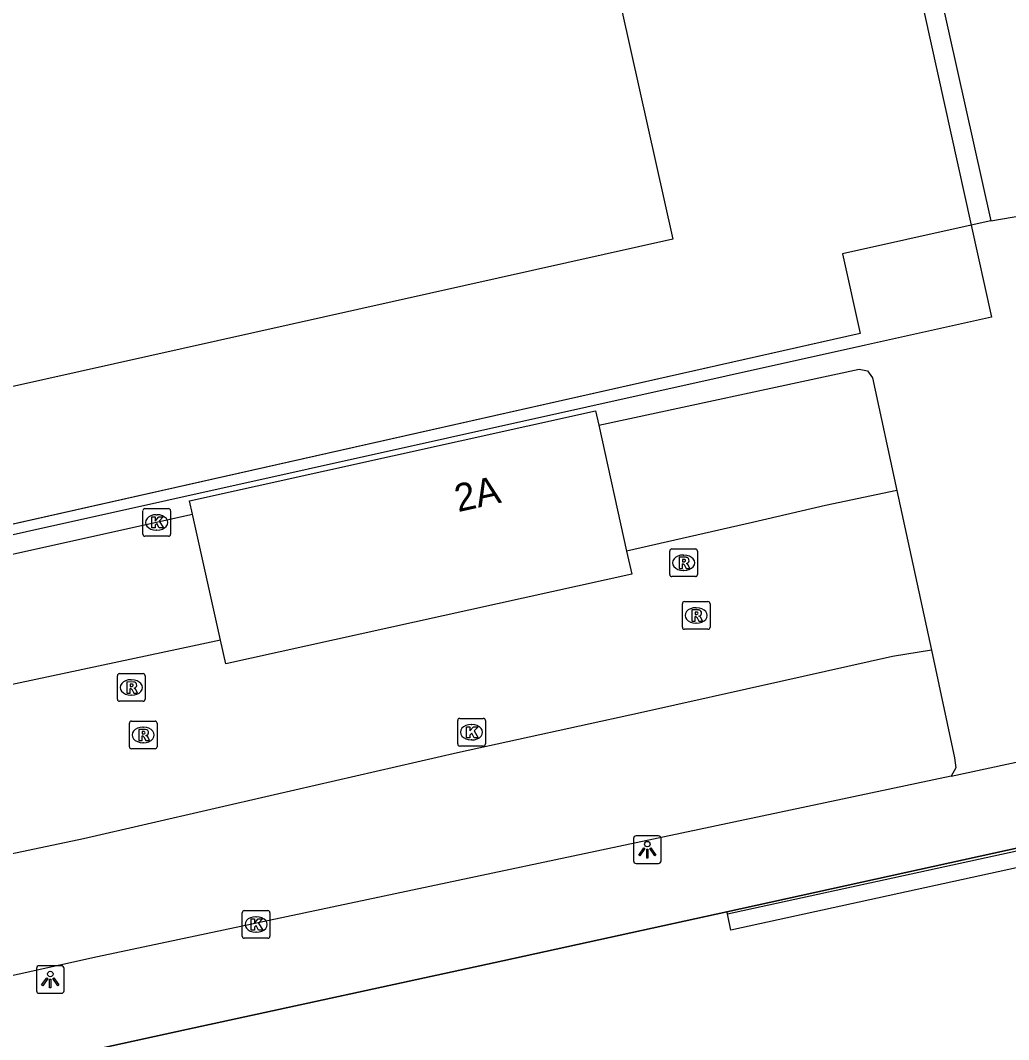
# Model space of a CAD drawing. Extents: x 160806 to 161707, y 383697 to 384148.
# Drawn here: x 161645.05 to 161680.77, y 383862.05 to 383898.89 of the extents above; entities that cross this region are included whole.
import ezdxf

# ---------------------------------------------------------------- set-up
doc = ezdxf.new("R2010")
doc.units = 0
for name, color, linetype in [('IMGEO_Grasland_overig', 7, 'Continuous'), ('IMGEO_Groenvoorziening', 7, 'Continuous'), ('IMGEO_Hek', 7, 'Continuous'), ('IMGEO_Kolk', 7, 'Continuous'), ('IMGEO_Lichtpunt', 7, 'Continuous'), ('IMGEO_Pand', 7, 'Continuous'), ('IMGEO_Pand_nummerreeks', 7, 'Continuous'), ('IMGEO_Parkeervlak_open', 7, 'Continuous'), ('IMGEO_Rijbaan_lokaal_open', 7, 'Continuous'), ('IMGEO_Rioolput', 7, 'Continuous'), ('IMGEO_Spoorbaan_halfverhard', 7, 'Continuous'), ('IMGEO_Terreindeel_gesloten', 7, 'Continuous')]:
    doc.layers.add(name, color=color, linetype=linetype)

msp = doc.modelspace()

# ---------------------------------------------------------------- linework, layer by layer
at = {"layer": 'IMGEO_Grasland_overig'}
msp.add_lwpolyline([(161679.423, 383891.492), (161680.158, 383888.167), (161675.596, 383887.152), (161635.195, 383878.161), (161630.532, 383877.228), (161606.363, 383871.769)], dxfattribs=at)
at = {"layer": 'IMGEO_Groenvoorziening'}
for points in [[(161661.841, 383973.012), (161664.529, 383961.571), (161680.134, 383891.651)], [(161680.134, 383891.651), (161686.383, 383892.722)], [(161680.134, 383891.651), (161679.423, 383891.492)], [(161678.693, 383871.571), (161692.17, 383874.476), (161696.167, 383872.737)], [(161692.46, 383871.911), (161687.731, 383870.454), (161682.93, 383869.376), (161670.593, 383866.669)]]:
    msp.add_lwpolyline(points, dxfattribs=at)
at = {"layer": 'IMGEO_Hek'}
for points in [[(161679.423, 383891.492), (161674.766, 383890.452), (161675.408, 383887.573), (161592.484, 383868.91)], [(161468.352, 383821.972), (161470.021, 383822.345), (161472.634, 383822.879), (161475.023, 383823.371), (161479.934, 383824.467), (161509.272, 383830.942), (161514.217, 383832.035), (161521.635, 383833.723), (161580.201, 383846.689), (161582.51, 383847.687), (161585.012, 383847.75), (161614.342, 383854.325), (161641.301, 383860.274), (161651.06, 383862.411), (161662.497, 383864.892), (161670.593, 383866.669), (161682.93, 383869.376), (161687.731, 383870.454), (161692.46, 383871.911), (161696.167, 383872.737)]]:
    msp.add_lwpolyline(points, dxfattribs=at)
at = {"layer": 'IMGEO_Kolk'}
for p, q in [((161649.479, 383880.317), (161649.479, 383881.169)), ((161649.554, 383881.243), (161650.406, 383881.243)), ((161650.48, 383881.169), (161650.48, 383880.317)), ((161649.967, 383881.023), (161649.992, 383881.023)), ((161649.99, 383880.463), (161649.965, 383880.463)), ((161650.406, 383880.243), (161649.554, 383880.243)), ((161660.935, 383873.66), (161661.787, 383873.66)), ((161660.86, 383872.734), (161660.86, 383873.586)), ((161661.348, 383873.44), (161661.373, 383873.44)), ((161661.861, 383873.586), (161661.861, 383872.734)), ((161661.787, 383872.66), (161660.935, 383872.66)), ((161661.371, 383872.88), (161661.346, 383872.88)), ((161653.148, 383866.709), (161654, 383866.709)), ((161653.073, 383865.783), (161653.073, 383866.635)), ((161653.561, 383866.489), (161653.586, 383866.489)), ((161654.074, 383866.635), (161654.074, 383865.783)), ((161653.584, 383865.929), (161653.559, 383865.929)), ((161654, 383865.709), (161653.148, 383865.709))]:
    msp.add_line(p, q, dxfattribs=at)
for points in [[(161649.479, 383880.317), (161649.479, 383881.169)], [(161649.554, 383881.243), (161650.406, 383881.243)], [(161650.48, 383881.169), (161650.48, 383880.317)], [(161649.8, 383880.943), (161649.923, 383880.943), (161649.923, 383880.792), (161650.053, 383880.943), (161650.217, 383880.943), (161650.071, 383880.792), (161650.224, 383880.543), (161650.072, 383880.543), (161649.987, 383880.707), (161649.923, 383880.64), (161649.923, 383880.543), (161649.8, 383880.543), (161649.8, 383880.943)], [(161650.406, 383880.243), (161649.554, 383880.243)], [(161660.935, 383873.66), (161661.787, 383873.66)], [(161660.86, 383872.734), (161660.86, 383873.586)], [(161661.181, 383873.36), (161661.304, 383873.36), (161661.304, 383873.209), (161661.434, 383873.36), (161661.598, 383873.36), (161661.452, 383873.209), (161661.605, 383872.96), (161661.453, 383872.96), (161661.368, 383873.124), (161661.304, 383873.057), (161661.304, 383872.96), (161661.181, 383872.96), (161661.181, 383873.36)], [(161661.861, 383873.586), (161661.861, 383872.734)], [(161661.787, 383872.66), (161660.935, 383872.66)], [(161653.148, 383866.709), (161654, 383866.709)], [(161653.073, 383865.783), (161653.073, 383866.635)], [(161653.394, 383866.409), (161653.517, 383866.409), (161653.517, 383866.258), (161653.647, 383866.409), (161653.811, 383866.409), (161653.665, 383866.258), (161653.818, 383866.009), (161653.666, 383866.009), (161653.581, 383866.173), (161653.517, 383866.106), (161653.517, 383866.009), (161653.394, 383866.009), (161653.394, 383866.409)], [(161654.074, 383866.635), (161654.074, 383865.783)], [(161654, 383865.709), (161653.148, 383865.709)]]:
    msp.add_lwpolyline(points, dxfattribs=at)
for centre, start, end in [((161649.556, 383881.167), 91.552, 178.448), ((161649.556, 383881.167), 91.552, 178.448), ((161650.404, 383881.167), 1.552, 88.448), ((161650.404, 383881.167), 1.552, 88.448), ((161649.556, 383880.319), 181.552, 268.448), ((161649.556, 383880.319), 181.552, 268.448), ((161650.404, 383880.319), 271.552, 358.448), ((161650.404, 383880.319), 271.552, 358.448), ((161660.937, 383873.584), 91.552, 178.448), ((161660.937, 383873.584), 91.552, 178.448), ((161661.785, 383873.584), 1.552, 88.448), ((161661.785, 383873.584), 1.552, 88.448), ((161660.937, 383872.736), 181.552, 268.448), ((161660.937, 383872.736), 181.552, 268.448), ((161661.785, 383872.736), 271.552, 358.448), ((161661.785, 383872.736), 271.552, 358.448), ((161653.15, 383866.633), 91.552, 178.448), ((161653.15, 383866.633), 91.552, 178.448), ((161653.998, 383866.633), 1.552, 88.448), ((161653.998, 383866.633), 1.552, 88.448), ((161653.15, 383865.785), 181.552, 268.448), ((161653.15, 383865.785), 181.552, 268.448), ((161653.998, 383865.785), 271.552, 358.448), ((161653.998, 383865.785), 271.552, 358.448)]:
    msp.add_arc(centre, 0.0765, start, end, dxfattribs=at)
for centre, major_axis, ratio, start_param, end_param in [((161649.966, 383880.743), (-0.387, 0.002), 0.722429, 4.712389, 7.853982), ((161649.991, 383880.743), (-0.39, 0.002), 0.717154, 1.570796, 4.712389), ((161661.347, 383873.16), (-0.387, 0.002), 0.722429, 4.712389, 7.853982), ((161661.372, 383873.16), (-0.39, 0.002), 0.717154, 1.570796, 4.712389), ((161653.56, 383866.209), (-0.387, 0.002), 0.722429, 4.712389, 7.853982), ((161653.585, 383866.209), (-0.39, 0.002), 0.717154, 1.570796, 4.712389)]:
    msp.add_ellipse(centre, major_axis=major_axis, ratio=ratio, start_param=start_param, end_param=end_param, dxfattribs=at)
at = {"layer": 'IMGEO_Lichtpunt'}
for p, q in [((161667.216, 383869.317), (161667.216, 383868.51)), ((161667.216, 383869.317), (161667.216, 383868.51)), ((161668.118, 383869.412), (161667.31, 383869.412)), ((161668.118, 383869.412), (161667.31, 383869.412)), ((161668.212, 383868.51), (161668.212, 383869.317)), ((161668.212, 383868.51), (161668.212, 383869.317)), ((161667.31, 383868.416), (161668.118, 383868.416)), ((161667.31, 383868.416), (161668.118, 383868.416)), ((161645.636, 383864.622), (161645.636, 383863.815)), ((161645.636, 383864.622), (161645.636, 383863.815)), ((161646.538, 383864.717), (161645.73, 383864.717)), ((161646.538, 383864.717), (161645.73, 383864.717)), ((161646.632, 383863.815), (161646.632, 383864.622)), ((161646.632, 383863.815), (161646.632, 383864.622)), ((161645.73, 383863.721), (161646.538, 383863.721)), ((161645.73, 383863.721), (161646.538, 383863.721))]:
    msp.add_line(p, q, dxfattribs=at)
for points in [[(161667.59, 383868.981), (161667.629, 383868.953), (161667.441, 383868.691), (161667.403, 383868.718), (161667.59, 383868.981)], [(161667.692, 383868.933), (161667.739, 383868.933), (161667.739, 383868.611), (161667.692, 383868.611), (161667.692, 383868.933)], [(161667.802, 383868.953), (161667.84, 383868.98), (161668.027, 383868.718), (161667.988, 383868.69), (161667.802, 383868.953)], [(161646.01, 383864.286), (161646.049, 383864.258), (161645.861, 383863.996), (161645.823, 383864.023), (161646.01, 383864.286)], [(161646.112, 383864.238), (161646.159, 383864.238), (161646.159, 383863.916), (161646.112, 383863.916), (161646.112, 383864.238)], [(161646.222, 383864.258), (161646.26, 383864.285), (161646.447, 383864.023), (161646.408, 383863.995), (161646.222, 383864.258)]]:
    msp.add_lwpolyline(points, dxfattribs=at)
for centre in [(161667.715, 383869.115), (161646.135, 383864.42)]:
    msp.add_circle(centre, 0.0994, dxfattribs=at)
for centre, start, end in [((161667.31, 383869.317), 90, 180), ((161667.31, 383869.317), 90, 180), ((161668.118, 383869.317), 0, 90), ((161668.118, 383869.317), 0, 90), ((161667.31, 383868.51), 180, 270), ((161667.31, 383868.51), 180, 270), ((161668.118, 383868.51), 270, 0), ((161668.118, 383868.51), 270, 360), ((161645.73, 383864.622), 90, 180), ((161645.73, 383864.622), 90, 180), ((161646.538, 383864.622), 0, 90), ((161646.538, 383864.622), 0, 90), ((161645.73, 383863.815), 180, 270), ((161645.73, 383863.815), 180, 270), ((161646.538, 383863.815), 270, 0), ((161646.538, 383863.815), 270, 360)]:
    msp.add_arc(centre, 0.0946, start, end, dxfattribs=at)
at = {"layer": 'IMGEO_Pand'}
for points in [[(161636.5, 383961.134), (161636.09, 383962.971), (161636.41, 383963.042), (161651.22, 383966.246), (161651.275, 383966.421), (161651.781, 383966.534), (161668.642, 383890.98), (161623.195, 383880.838), (161623.29, 383880.412), (161614.09, 383878.359)], [(161651.274, 383881.048), (161651.168, 383881.526), (161665.845, 383884.775), (161665.96, 383884.257)], [(161665.96, 383884.257), (161666.967, 383879.708)], [(161652.29, 383876.485), (161651.274, 383881.048)], [(161666.967, 383879.708), (161667.151, 383878.878), (161652.481, 383875.629), (161652.29, 383876.485)]]:
    msp.add_lwpolyline(points, dxfattribs=at)
at = {"layer": 'IMGEO_Parkeervlak_open'}
for points in [[(161665.96, 383884.257), (161675.376, 383886.281), (161675.673, 383886.219), (161675.855, 383885.976), (161676.735, 383881.898)], [(161606.519, 383871.073), (161626.185, 383875.445), (161628.76, 383876.043), (161651.274, 383881.048)], [(161677.981, 383876.124), (161678.822, 383872.229), (161678.868, 383871.878), (161678.693, 383871.571)], [(161678.693, 383871.571), (161647.839, 383865.039), (161626.972, 383860.422), (161609.694, 383856.527), (161595.494, 383853.326)]]:
    msp.add_lwpolyline(points, dxfattribs=at)
at = {"layer": 'IMGEO_Rijbaan_lokaal_open'}
for points in [[(161655.739, 383972.541), (161658.016, 383963.339), (161663.04, 383964.457), (161672.626, 383922.253), (161679.423, 383891.492)], [(161679.423, 383891.492), (161674.766, 383890.452), (161675.408, 383887.573), (161606.306, 383872.021)], [(161676.735, 383881.898), (161674.153, 383881.35), (161671.512, 383880.738), (161666.967, 383879.708)], [(161676.735, 383881.898), (161677.981, 383876.124)], [(161652.29, 383876.485), (161651.442, 383876.303), (161629.63, 383871.673), (161606.594, 383866.552), (161606.493, 383866.529), (161603.52, 383865.895), (161591.531, 383863.209)], [(161677.981, 383876.124), (161676.579, 383875.892), (161672.537, 383874.994), (161667.473, 383873.86), (161660.853, 383872.411), (161654.242, 383870.901), (161647.339, 383869.306), (161629.555, 383865.552), (161607.736, 383860.676), (161592.972, 383857.432)]]:
    msp.add_lwpolyline(points, dxfattribs=at)
at = {"layer": 'IMGEO_Rioolput'}
for p, q in [((161668.527, 383878.858), (161668.527, 383879.71)), ((161668.602, 383879.784), (161669.454, 383879.784)), ((161669.015, 383879.564), (161669.04, 383879.564)), ((161669.528, 383879.71), (161669.528, 383878.858)), ((161669.038, 383879.004), (161669.013, 383879.004)), ((161669.454, 383878.784), (161668.602, 383878.784)), ((161668.981, 383876.954), (161668.981, 383877.806)), ((161669.056, 383877.88), (161669.908, 383877.88)), ((161669.982, 383877.806), (161669.982, 383876.954)), ((161669.469, 383877.66), (161669.494, 383877.66)), ((161669.492, 383877.1), (161669.467, 383877.1)), ((161669.908, 383876.88), (161669.056, 383876.88)), ((161648.563, 383874.351), (161648.563, 383875.203)), ((161648.638, 383875.277), (161649.49, 383875.277)), ((161649.564, 383875.203), (161649.564, 383874.351)), ((161649.051, 383875.057), (161649.076, 383875.057)), ((161649.074, 383874.497), (161649.049, 383874.497)), ((161649.49, 383874.277), (161648.638, 383874.277)), ((161648.993, 383872.635), (161648.993, 383873.487)), ((161649.068, 383873.561), (161649.92, 383873.561)), ((161649.481, 383873.341), (161649.506, 383873.341)), ((161649.994, 383873.487), (161649.994, 383872.635)), ((161649.92, 383872.561), (161649.068, 383872.561)), ((161649.504, 383872.781), (161649.479, 383872.781))]:
    msp.add_line(p, q, dxfattribs=at)
for points in [[(161668.527, 383878.858), (161668.527, 383879.71)], [(161668.602, 383879.784), (161669.454, 383879.784)], [(161669.528, 383879.71), (161669.528, 383878.858)], [(161669.116, 383879.482), (161668.864, 383879.484), (161668.864, 383879.084)], [(161668.864, 383879.084), (161668.988, 383879.084), (161668.988, 383879.246), (161668.999, 383879.246)], [(161669.042, 383879.403), (161668.988, 383879.403), (161668.988, 383879.322)], [(161668.988, 383879.322), (161669.04, 383879.322)], [(161669.046, 383879.217), (161669.117, 383879.084), (161669.257, 383879.084), (161669.192, 383879.21)], [(161669.454, 383878.784), (161668.602, 383878.784)], [(161668.981, 383876.954), (161668.981, 383877.806)], [(161669.056, 383877.88), (161669.908, 383877.88)], [(161669.982, 383877.806), (161669.982, 383876.954)], [(161669.57, 383877.578), (161669.318, 383877.58), (161669.318, 383877.18)], [(161669.496, 383877.499), (161669.442, 383877.499), (161669.442, 383877.418)], [(161669.442, 383877.418), (161669.494, 383877.418)], [(161669.318, 383877.18), (161669.442, 383877.18), (161669.442, 383877.342), (161669.453, 383877.342)], [(161669.5, 383877.313), (161669.571, 383877.18), (161669.711, 383877.18), (161669.646, 383877.306)], [(161669.908, 383876.88), (161669.056, 383876.88)], [(161648.563, 383874.351), (161648.563, 383875.203)], [(161648.638, 383875.277), (161649.49, 383875.277)], [(161649.564, 383875.203), (161649.564, 383874.351)], [(161649.152, 383874.975), (161648.9, 383874.977), (161648.9, 383874.577)], [(161649.078, 383874.896), (161649.024, 383874.896), (161649.024, 383874.815)], [(161649.024, 383874.815), (161649.076, 383874.815)], [(161648.9, 383874.577), (161649.024, 383874.577), (161649.024, 383874.739), (161649.035, 383874.739)], [(161649.082, 383874.71), (161649.153, 383874.577), (161649.293, 383874.577), (161649.228, 383874.703)], [(161649.49, 383874.277), (161648.638, 383874.277)], [(161648.993, 383872.635), (161648.993, 383873.487)], [(161649.068, 383873.561), (161649.92, 383873.561)], [(161649.994, 383873.487), (161649.994, 383872.635)], [(161649.582, 383873.259), (161649.33, 383873.261), (161649.33, 383872.861)], [(161649.33, 383872.861), (161649.454, 383872.861), (161649.454, 383873.023), (161649.465, 383873.023)], [(161649.508, 383873.18), (161649.454, 383873.18), (161649.454, 383873.099)], [(161649.454, 383873.099), (161649.506, 383873.099)], [(161649.512, 383872.994), (161649.583, 383872.861), (161649.723, 383872.861), (161649.658, 383872.987)], [(161649.92, 383872.561), (161649.068, 383872.561)]]:
    msp.add_lwpolyline(points, dxfattribs=at)
for centre, radius, start, end in [((161668.604, 383879.708), 0.0765, 91.552, 178.448), ((161668.604, 383879.708), 0.0765, 91.552, 178.448), ((161669.452, 383879.708), 0.0765, 1.552, 88.448), ((161669.452, 383879.708), 0.0765, 1.552, 88.448), ((161668.998, 383879.193), 0.0533, 26.0293, 88.6989), ((161669.024, 383879.511), 0.19, 274.7715, 282.9687), ((161669.048, 383879.307), 0.0964, 77.0061, 93.1865), ((161669.062, 383879.364), 0.0378, 276.6634, 79.6772), ((161669.115, 383879.372), 0.109, 350.3612, 89.416), ((161669.113, 383879.372), 0.112, 277.5842, 350.9817), ((161669.097, 383879.157), 0.108, 29.5134, 73.7905), ((161668.604, 383878.86), 0.0765, 181.552, 268.448), ((161668.604, 383878.86), 0.0765, 181.552, 268.448), ((161669.452, 383878.86), 0.0765, 271.552, 358.448), ((161669.452, 383878.86), 0.0765, 271.552, 358.448), ((161669.058, 383877.804), 0.0765, 91.552, 178.448), ((161669.058, 383877.804), 0.0765, 91.552, 178.448), ((161669.906, 383877.804), 0.0765, 1.552, 88.448), ((161669.906, 383877.804), 0.0765, 1.552, 88.448), ((161669.478, 383877.607), 0.19, 274.7715, 282.9687), ((161669.502, 383877.403), 0.0964, 77.0061, 93.1865), ((161669.516, 383877.46), 0.0378, 276.6634, 79.6772), ((161669.569, 383877.468), 0.109, 350.3612, 89.416), ((161669.567, 383877.468), 0.112, 277.5842, 350.9817), ((161669.551, 383877.253), 0.108, 29.5134, 73.7905), ((161669.452, 383877.289), 0.0533, 26.0293, 88.6989), ((161669.058, 383876.956), 0.0765, 181.552, 268.448), ((161669.058, 383876.956), 0.0765, 181.552, 268.448), ((161669.906, 383876.956), 0.0765, 271.552, 358.448), ((161669.906, 383876.956), 0.0765, 271.552, 358.448), ((161648.64, 383875.201), 0.0765, 91.552, 178.448), ((161648.64, 383875.201), 0.0765, 91.552, 178.448), ((161649.488, 383875.201), 0.0765, 1.552, 88.448), ((161649.488, 383875.201), 0.0765, 1.552, 88.448), ((161649.06, 383875.004), 0.19, 274.7715, 282.9687), ((161649.084, 383874.8), 0.0964, 77.0061, 93.1865), ((161649.098, 383874.857), 0.0378, 276.6634, 79.6772), ((161649.151, 383874.865), 0.109, 350.3612, 89.416), ((161649.149, 383874.865), 0.112, 277.5842, 350.9817), ((161649.034, 383874.686), 0.0533, 26.0293, 88.6989), ((161649.133, 383874.65), 0.108, 29.5134, 73.7905), ((161648.64, 383874.353), 0.0765, 181.552, 268.448), ((161648.64, 383874.353), 0.0765, 181.552, 268.448), ((161649.488, 383874.353), 0.0765, 271.552, 358.448), ((161649.488, 383874.353), 0.0765, 271.552, 358.448), ((161649.07, 383873.485), 0.0765, 91.552, 178.448), ((161649.07, 383873.485), 0.0765, 91.552, 178.448), ((161649.918, 383873.485), 0.0765, 1.552, 88.448), ((161649.918, 383873.485), 0.0765, 1.552, 88.448), ((161649.464, 383872.97), 0.0533, 26.0293, 88.6989), ((161649.49, 383873.288), 0.19, 274.7715, 282.9687), ((161649.514, 383873.084), 0.0964, 77.0061, 93.1865), ((161649.528, 383873.141), 0.0378, 276.6634, 79.6772), ((161649.581, 383873.149), 0.109, 350.3612, 89.416), ((161649.579, 383873.149), 0.112, 277.5842, 350.9817), ((161649.563, 383872.934), 0.108, 29.5134, 73.7905), ((161649.07, 383872.637), 0.0765, 181.552, 268.448), ((161649.07, 383872.637), 0.0765, 181.552, 268.448), ((161649.918, 383872.637), 0.0765, 271.552, 358.448), ((161649.918, 383872.637), 0.0765, 271.552, 358.448)]:
    msp.add_arc(centre, radius, start, end, dxfattribs=at)
for centre, major_axis, ratio, start_param, end_param in [((161669.014, 383879.284), (-0.387, 0.002), 0.722429, 4.712389, 7.853982), ((161669.039, 383879.284), (-0.39, 0.002), 0.717154, 1.570796, 4.712389), ((161669.468, 383877.38), (-0.387, 0.002), 0.722429, 4.712389, 7.853982), ((161669.493, 383877.38), (-0.39, 0.002), 0.717154, 1.570796, 4.712389), ((161649.05, 383874.777), (-0.387, 0.002), 0.722429, 4.712389, 7.853982), ((161649.075, 383874.777), (-0.39, 0.002), 0.717154, 1.570796, 4.712389), ((161649.48, 383873.061), (-0.387, 0.002), 0.722429, 4.712389, 7.853982), ((161649.505, 383873.061), (-0.39, 0.002), 0.717154, 1.570796, 4.712389)]:
    msp.add_ellipse(centre, major_axis=major_axis, ratio=ratio, start_param=start_param, end_param=end_param, dxfattribs=at)
at = {"layer": 'IMGEO_Spoorbaan_halfverhard'}
for points in [[(161693.023, 383869.99), (161692.62, 383870.112), (161688.454, 383869.869), (161670.738, 383866.006), (161670.61, 383866.592)], [(161670.593, 383866.669), (161662.497, 383864.892), (161651.06, 383862.411), (161641.301, 383860.274), (161614.342, 383854.325), (161585.012, 383847.75), (161582.51, 383847.687), (161580.201, 383846.689), (161521.635, 383833.723), (161514.217, 383832.035), (161509.272, 383830.942), (161479.934, 383824.467), (161475.023, 383823.371), (161472.634, 383822.879), (161470.021, 383822.345), (161468.352, 383821.972)], [(161670.61, 383866.592), (161670.593, 383866.669)]]:
    msp.add_lwpolyline(points, dxfattribs=at)
at = {"layer": 'IMGEO_Terreindeel_gesloten'}
msp.add_lwpolyline([(161670.61, 383866.592), (161688.372, 383870.466), (161692.862, 383870.727)], dxfattribs=at)

# ---------------------------------------------------------------- texts
at = {"layer": 'IMGEO_Pand_nummerreeks'}
msp.add_text('2A', height=1, rotation=12.4848, dxfattribs=at).set_placement((161660.874, 383881.114))

doc.saveas('drawing.dxf')
